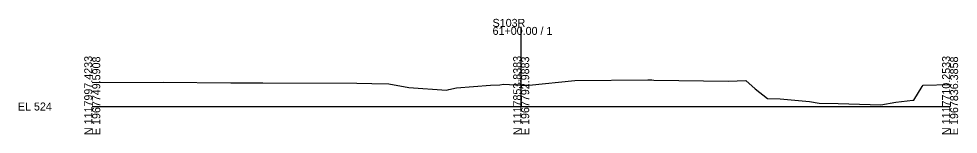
# Model space of a CAD drawing. Extents: x 974 to 1303, y 990 to 10019.
# Drawn here: x 974.3 to 1302.8, y 3490.3 to 3530.7 of the extents above; entities that cross this region are included whole.
import ezdxf

# ---------------------------------------------------------------- set-up
doc = ezdxf.new("R2010")
doc.units = 0
for name, color, linetype in [('Level 10', 7, 'Continuous'), ('Level 60', 7, 'Continuous'), ('Level 63', 7, 'Continuous')]:
    doc.layers.add(name, color=color, linetype=linetype)

msp = doc.modelspace()

# ---------------------------------------------------------------- linework, layer by layer
at = {"layer": 'Level 60'}
for p, q in [((1152.85, 3507.48), (1168.74, 3509.12)), ((1168.74, 3509.12), (1194.35, 3509.28)), ((1194.35, 3509.28), (1195.75, 3509.28)), ((1195.75, 3509.28), (1196.4, 3509.25)), ((1196.4, 3509.25), (1222.47, 3508.91)), ((1222.47, 3508.91), (1228.57, 3509.08)), ((1228.57, 3509.08), (1231.81, 3506.15)), ((1000, 3508.39), (1024.78, 3508.47)), ((1024.78, 3508.47), (1048.44, 3508.25)), ((1048.44, 3508.25), (1056.66, 3508.26)), ((1056.66, 3508.26), (1058.83, 3508.28)), ((1058.83, 3508.28), (1059.68, 3508.29)), ((1059.68, 3508.29), (1092.49, 3508.14)), ((1092.49, 3508.14), (1097.78, 3508.06)), ((1097.78, 3508.06), (1103.69, 3507.97)), ((1103.69, 3507.97), (1110.67, 3506.67)), ((1110.67, 3506.67), (1123.89, 3505.67)), ((1123.89, 3505.67), (1124.66, 3505.93)), ((1124.66, 3505.93), (1127.43, 3506.55)), ((1127.43, 3506.55), (1139.26, 3507.47)), ((1139.26, 3507.47), (1142.54, 3507.62)), ((1142.54, 3507.62), (1143.78, 3507.84)), ((1143.78, 3507.84), (1150.11, 3507.42)), ((1150.11, 3507.42), (1152.85, 3507.48)), ((1231.81, 3506.15), (1236.09, 3502.79)), ((1287.34, 3502.24), (1290.27, 3507.01)), ((1290.27, 3507.01), (1290.6, 3507.5)), ((1290.6, 3507.5), (1300, 3507.74)), ((1236.09, 3502.79), (1240.56, 3502.64)), ((1240.56, 3502.64), (1250.82, 3501.73)), ((1281.04, 3501.49), (1287.01, 3502.21)), ((1287.01, 3502.21), (1287.34, 3502.24)), ((1250.82, 3501.73), (1254.27, 3501.21)), ((1254.27, 3501.21), (1260.88, 3501)), ((1260.88, 3501), (1275.73, 3500.55)), ((1275.73, 3500.55), (1281.04, 3501.49))]:
    msp.add_line(p, q, dxfattribs=at)
at = {"layer": 'Level 63'}
for p, q in [((1150, 3500), (1150, 3527.85)), ((1000, 3500), (1150, 3500)), ((1150, 3500), (1300, 3500))]:
    msp.add_line(p, q, dxfattribs=at)

# ---------------------------------------------------------------- texts
at = {"layer": 'Level 10'}
msp.add_text('531.43', height=0.9, rotation=90, dxfattribs=at).set_placement((1149.95, 3507.93))
at = {"layer": 'Level 63'}
for s, p in [('S103R', (1140, 3527.85)), ('61+00.00 / 1', (1140, 3525.05)), ('EL 524', (974, 3498.6))]:
    msp.add_text(s, height=2.8, dxfattribs=at).set_placement(p)
for s, p in [('N 1117997.4233', (1000, 3490)), ('E 1967749.5908', (1002.8, 3490)), ('N 1117853.8383', (1150, 3490)), ('E 1967792.9883', (1152.8, 3490)), ('N 1117710.2533', (1300, 3490)), ('E 1967836.3858', (1302.8, 3490))]:
    msp.add_text(s, height=2.8, rotation=90, dxfattribs=at).set_placement(p)

doc.saveas('drawing.dxf')
